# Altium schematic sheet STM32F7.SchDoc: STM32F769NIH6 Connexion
size A3; Date: 29-OCT-2015; Author: A.B; CompanyName: STMicroelectronics; Organization: MCD/TOOLS/GNB; Address1: 12, Rue Jules HOROWITZ; Address2: 38019 Grenoble; Address3: FRANCE; DocumentNumber: MB1225; Revision: B-01; SheetNumber: 4; SheetTotal: 13; Project: STM32F769I-DISCO
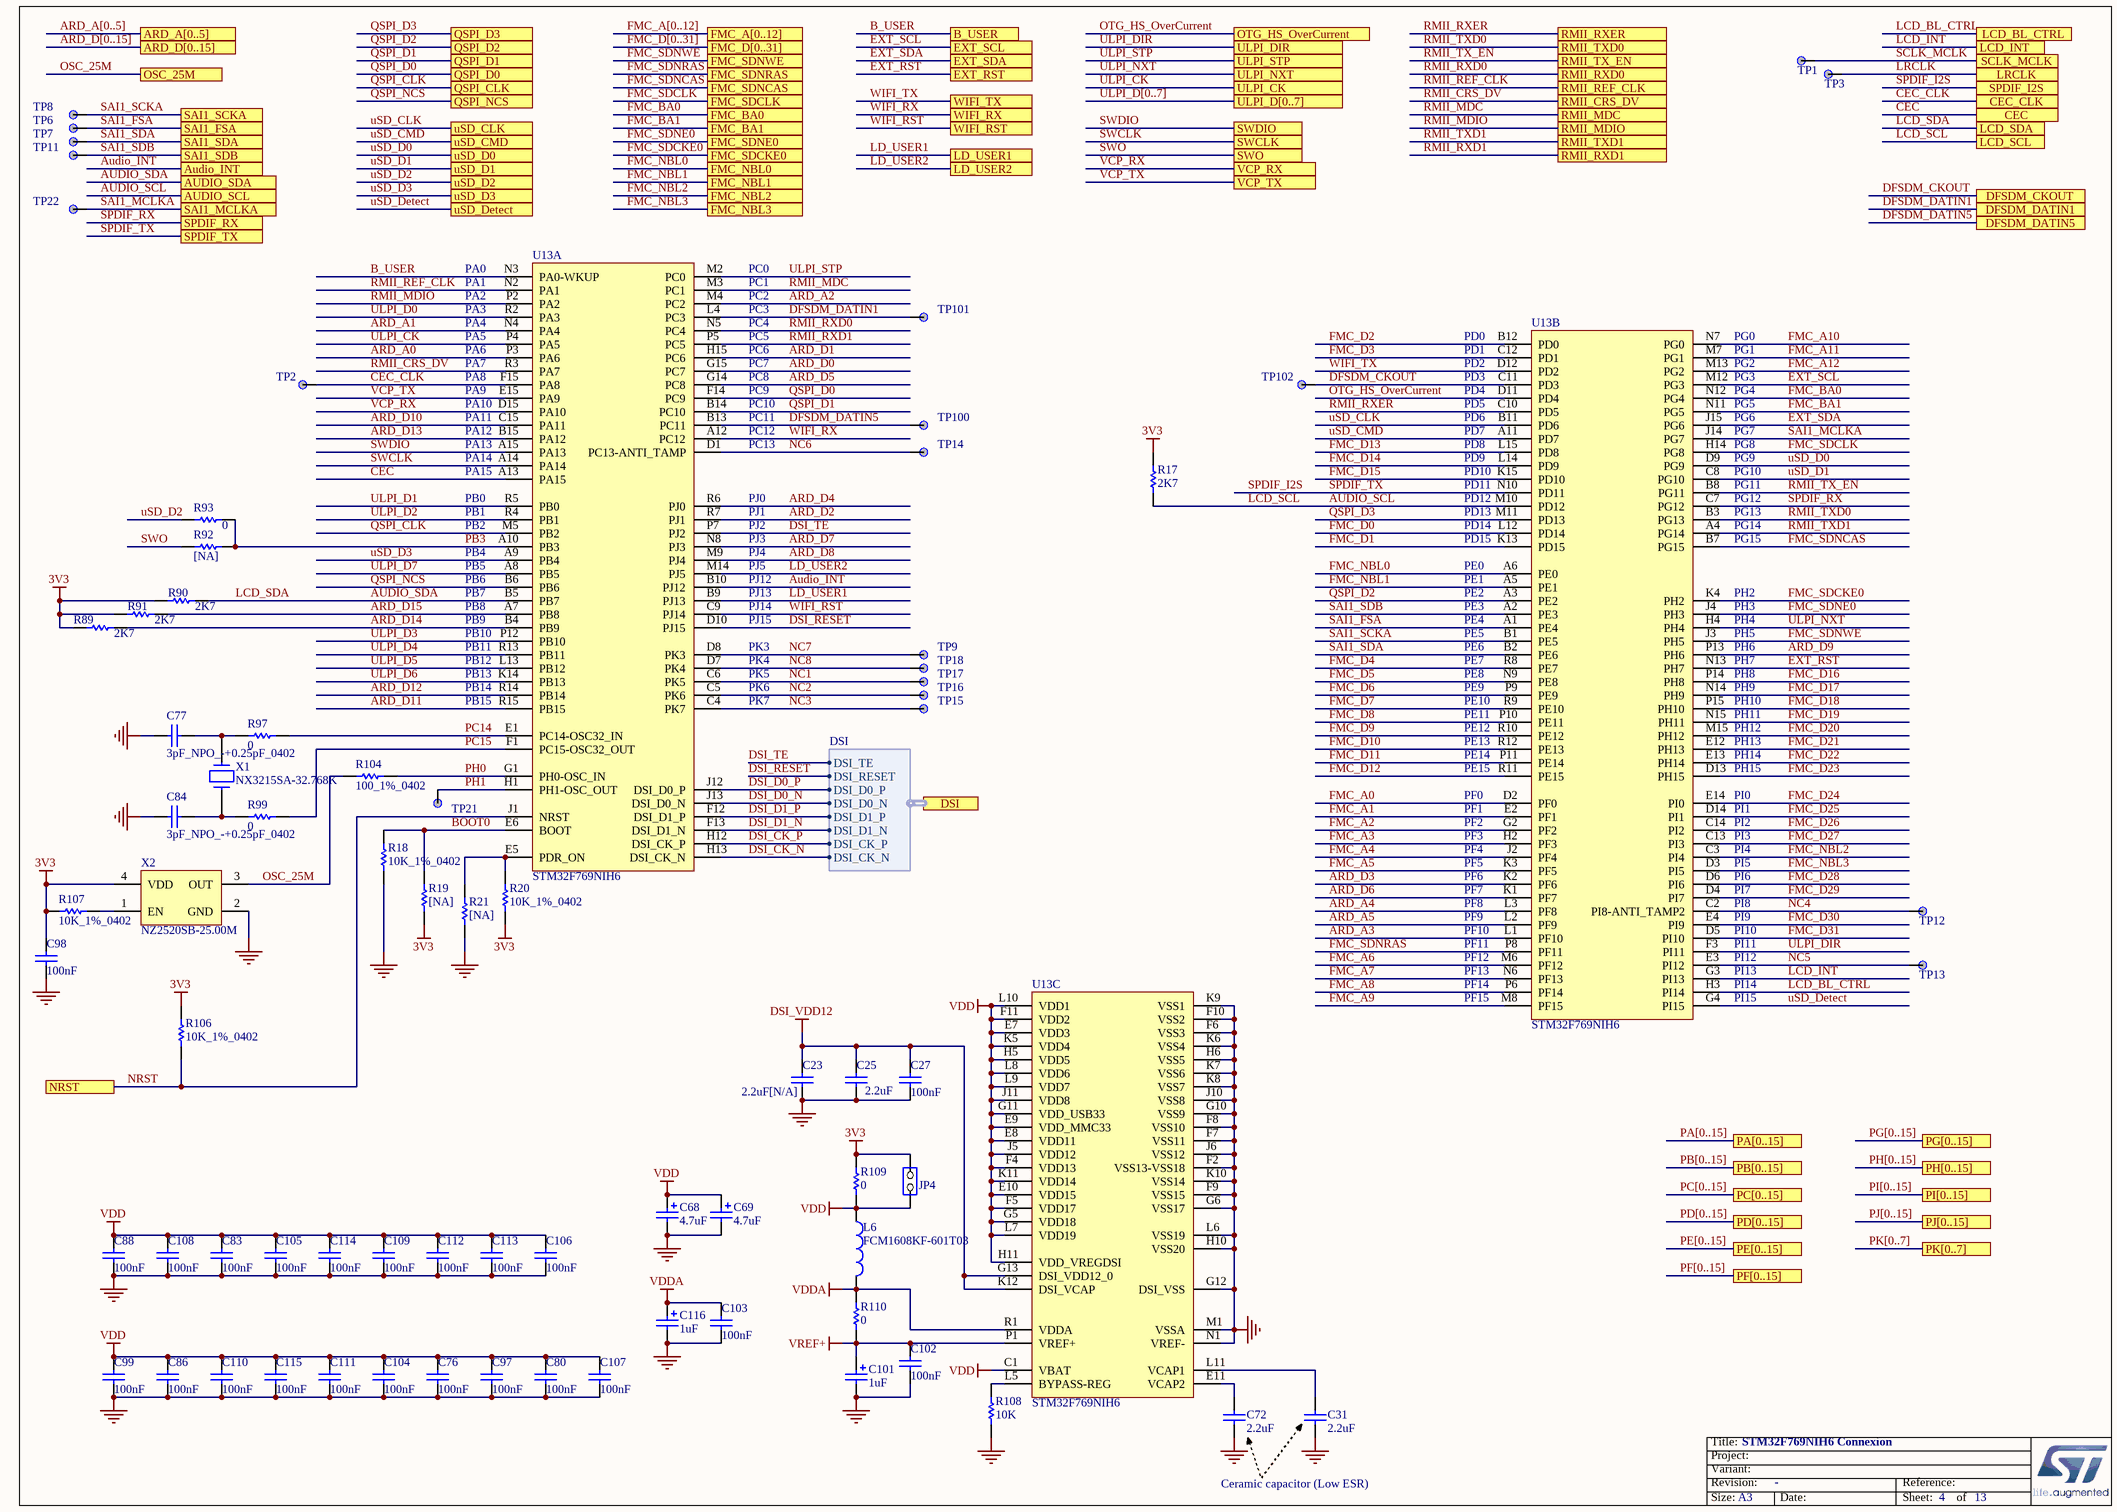
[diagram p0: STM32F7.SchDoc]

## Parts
C23  2.2uF[N/A]  [1206C]
C25  2.2uF  [0603C]
C27  100nF  [0402C]
C31  2.2uF  [1206C]
C68  4.7uF  [TAN-A]
C69  4.7uF  [TAN-A]
C72  2.2uF  [1206C]
C76  100nF  [0402C]
C77  3pF_NPO_-+0.25pF_0402  [0402C]
C80  100nF  [0402C]
C83  100nF  [0402C]
C84  3pF_NPO_-+0.25pF_0402  [0402C]
C86  100nF  [0402C]
C88  100nF  [0402C]
C97  100nF  [0402C]
C98  100nF  [0402C]
C99  100nF  [0402C]
C101  1uF  [TAN-A]
C102  100nF  [0402C]
C103  100nF  [0402C]
C104  100nF  [0402C]
C105  100nF  [0402C]
C106  100nF  [0402C]
C107  100nF  [0402C]
C108  100nF  [0402C]
C109  100nF  [0402C]
C110  100nF  [0402C]
C111  100nF  [0402C]
C112  100nF  [0402C]
C113  100nF  [0402C]
C114  100nF  [0402C]
C115  100nF  [0402C]
C116  1uF  [TAN-A]
JP4  JP2  [SIP2]  (value not drawn)
L6  FCM1608KF-601T03  [0603L]
R17  2K7  [0402R]
R18  10K_1%_0402  [0402R]
R19  [NA]  [0402R]
R20  10K_1%_0402  [0402R]
R21  [NA]  [0402R]
R89  2K7  [0402R]
R90  2K7  [0402R]
R91  2K7  [0402R]
R92  [NA]  [0402R]
R93  0  [0402R]
R97  0  [0402R]
R99  0  [0402R]
R104  100_1%_0402  [0402R]
R106  10K_1%_0402  [0402R]
R107  10K_1%_0402  [0402R]
R108  10K  [0402R]
R109  0  [0603R-GS]
R110  0  [0603R-GS]
TP1  TP  [TP_C40]  (value not drawn)
TP2  TP  [TP_C40]  (value not drawn)
TP3  TP  [TP_C40]  (value not drawn)
TP6  TP  [TP_C40]  (value not drawn)
TP7  TP  [TP_C40]  (value not drawn)
TP8  TP  [TP_C40]  (value not drawn)
TP9  TP  [TP_C40]  (value not drawn)
TP11  TP  [TP_C40]  (value not drawn)
TP12  TP  [TP_C40]  (value not drawn)
TP13  TP  [TP_C40]  (value not drawn)
TP14  TP  [TP_C40]  (value not drawn)
TP15  TP  [TP_C40]  (value not drawn)
TP16  TP  [TP_C40]  (value not drawn)
TP17  TP  [TP_C40]  (value not drawn)
TP18  TP  [TP_C40]  (value not drawn)
TP21  TP  [TP_C40]  (value not drawn)
TP22  TP  [TP_C40]  (value not drawn)
TP100  TP  [TP_C40]  (value not drawn)
TP101  TP  [TP_C40]  (value not drawn)
TP102  TP  [TP_C40]  (value not drawn)
U13  STM32F769NIH6  [BGA216_0R8_13X13]  (parts A,B,C of 3)
X1  NX3215SA-32.768K  [XTAL_2SM_3R2X1R5]
X2  NZ2520SB-25.00M  [OSC_4SM_2R5X2]

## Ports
ARD_A[0..5], ARD_D[0..15], Audio_INT, AUDIO_SCL, AUDIO_SDA, B_USER, CEC, CEC_CLK, DFSDM_CKOUT, DFSDM_DATIN1, DFSDM_DATIN5, DSI (harness DSI), EXT_RST, EXT_SCL, EXT_SDA, FMC_A[0..12], FMC_BA0, FMC_BA1, FMC_D[0..31], FMC_NBL0, FMC_NBL1, FMC_NBL2, FMC_NBL3, FMC_SDCKE0, FMC_SDCLK, FMC_SDNCAS, FMC_SDNE0, FMC_SDNRAS, FMC_SDNWE, LCD_BL_CTRL, LCD_INT, LCD_SCL, LCD_SDA, LD_USER1, LD_USER2, LRCLK, NRST, OSC_25M, OTG_HS_OverCurrent, PA[0..15], PB[0..15], PC[0..15], PD[0..15], PE[0..15], PF[0..15], PG[0..15], PH[0..15], PI[0..15], PJ[0..15], PK[0..7], QSPI_CLK, QSPI_D0, QSPI_D1, QSPI_D2, QSPI_D3, QSPI_NCS, RMII_CRS_DV, RMII_MDC, RMII_MDIO, RMII_REF_CLK, RMII_RXD0, RMII_RXD1, RMII_RXER, RMII_TX_EN, RMII_TXD0, RMII_TXD1, SAI1_FSA, SAI1_MCLKA, SAI1_SCKA, SAI1_SDA, SAI1_SDB, SCLK_MCLK, SPDIF_I2S, SPDIF_RX, SPDIF_TX, SWCLK, SWDIO, SWO, ULPI_CK, ULPI_D[0..7], ULPI_DIR, ULPI_NXT, ULPI_STP, uSD_CLK, uSD_CMD, uSD_D0, uSD_D1, uSD_D2, uSD_D3, uSD_Detect, VCP_RX, VCP_TX, WIFI_RST, WIFI_RX, WIFI_TX

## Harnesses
DSI: DSI_CK_P, DSI_CK_N, DSI_D0_P, DSI_D0_N, DSI_D1_P, DSI_D1_N, DSI_TE, DSI_RESET

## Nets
3V3: C98.2 JP4.2(NO) R17.2 R19.1 R20.1 R89.1 R90.1 R91.1 R106.2 R107.1 R109.2 X2.4(VDD)
DSI_VDD12: C23.2 C25.2 C27.2 U13.G13(DSI_VDD12_0) U13.K12(DSI_VCAP)
GND: C23.1 C25.1 C27.1 C31.1 C68.2 C69.2 C72.1 C76.1 C77.1 C80.1 C83.1 C84.1 C86.1 C88.1 C97.1 C98.1 C99.1 C101.2 C102.1 C103.1 C104.1 C105.1 C106.1 C107.1 C108.1 C109.1 C110.1 C111.1 C112.1 C113.1 C114.1 C115.1 C116.2 R18.1 R21.1 R108.1 U13.F2(VSS13-VSS18) U13.F6(VSS3) U13.F7(VSS11) U13.F8(VSS10) U13.F9(VSS15) U13.F10(VSS2) U13.G6(VSS17) U13.G10(VSS9) U13.G12(DSI_VSS) U13.H6(VSS5) U13.H10(VSS20) U13.J6(VSS12) U13.J10(VSS8) U13.K6(VSS4) U13.K7(VSS6) U13.K8(VSS7) U13.K9(VSS1) U13.K10(VSS14) U13.L6(VSS19) U13.M1(VSSA) U13.N1(VREF-) X2.2(GND)
VDD: C68.1 C69.1 C76.2 C80.2 C83.2 C86.2 C88.2 C97.2 C99.2 C104.2 C105.2 C106.2 C107.2 C108.2 C109.2 C110.2 C111.2 C112.2 C113.2 C114.2 C115.2 JP4.1(COMMON) L6.1 R109.1 U13.C1(VBAT) U13.E7(VDD3) U13.E8(VDD11) U13.E9(VDD_MMC33) U13.E10(VDD15) U13.F4(VDD13) U13.F5(VDD17) U13.F11(VDD2) U13.G5(VDD18) U13.G11(VDD_USB33) U13.H5(VDD5) U13.H11(VDD_VREGDSI) U13.J5(VDD12) U13.J11(VDD8) U13.K5(VDD4) U13.K11(VDD14) U13.L7(VDD19) U13.L8(VDD6) U13.L9(VDD7) U13.L10(VDD1)
VDDA: C103.2 C116.1 L6.2 R110.1 U13.R1(VDDA)
VREF+: C101.1 C102.2 R110.2 U13.P1(VREF+)
ARD_A0: U13.P3(PA6)
ARD_A1: U13.N4(PA4)
ARD_A2: U13.M4(PC2)
ARD_A3: U13.L1(PF10)
ARD_A4: U13.L3(PF8)
ARD_A5: U13.L2(PF9)
ARD_D0: U13.G15(PC7)
ARD_D1: U13.H15(PC6)
ARD_D2: U13.R7(PJ1)
ARD_D3: U13.K2(PF6)
ARD_D4: U13.R6(PJ0)
ARD_D5: U13.G14(PC8)
ARD_D6: U13.K1(PF7)
ARD_D7: U13.N8(PJ3)
ARD_D8: U13.M9(PJ4)
ARD_D9: U13.P13(PH6)
ARD_D10: U13.C15(PA11)
ARD_D11: U13.R15(PB15)
ARD_D12: U13.R14(PB14)
ARD_D13: U13.B15(PA12)
ARD_D14: R89.2 U13.B4(PB9)
ARD_D15: R91.2 U13.A7(PB8)
Audio_INT: U13.B10(PJ12) ; port Audio_INT
AUDIO_SCL: R17.1 U13.M10(PD12) ; port AUDIO_SCL, port LCD_SCL  [also labelled LCD_SCL]
AUDIO_SDA: R90.2 U13.B5(PB7) ; port AUDIO_SDA, port LCD_SDA  [also labelled LCD_SDA]
B_USER: U13.N3(PA0-WKUP) ; port B_USER
BOOT0: R18.2 R19.2 U13.E6(BOOT)
CEC: U13.A13(PA15) ; port CEC
CEC_CLK: TP2.1 U13.F15(PA8) ; port CEC_CLK
DFSDM_CKOUT: TP102.1 U13.C11(PD3) ; port DFSDM_CKOUT
DFSDM_DATIN1: TP101.1 U13.L4(PC3) ; port DFSDM_DATIN1
DFSDM_DATIN5: TP100.1 U13.B13(PC11) ; port DFSDM_DATIN5
DSI_CK_N: U13.H13(DSI_CK_N) ; port DSI.DSI_CK_N
DSI_CK_P: U13.H12(DSI_CK_P) ; port DSI.DSI_CK_P
DSI_D0_N: U13.J13(DSI_D0_N) ; port DSI.DSI_D0_N
DSI_D0_P: U13.J12(DSI_D0_P) ; port DSI.DSI_D0_P
DSI_D1_N: U13.F13(DSI_D1_N) ; port DSI.DSI_D1_N
DSI_D1_P: U13.F12(DSI_D1_P) ; port DSI.DSI_D1_P
DSI_RESET: U13.D10(PJ15) ; port DSI.DSI_RESET
DSI_TE: U13.P7(PJ2) ; port DSI.DSI_TE
EXT_RST: U13.N13(PH7) ; port EXT_RST
EXT_SCL: U13.M12(PG3) ; port EXT_SCL
EXT_SDA: U13.J15(PG6) ; port EXT_SDA
FMC_A0: U13.D2(PF0)
FMC_A1: U13.E2(PF1)
FMC_A2: U13.G2(PF2)
FMC_A3: U13.H2(PF3)
FMC_A4: U13.J2(PF4)
FMC_A5: U13.K3(PF5)
FMC_A6: U13.M6(PF12)
FMC_A7: U13.N6(PF13)
FMC_A8: U13.P6(PF14)
FMC_A9: U13.M8(PF15)
FMC_A10: U13.N7(PG0)
FMC_A11: U13.M7(PG1)
FMC_A12: U13.M13(PG2)
FMC_BA0: U13.N12(PG4) ; port FMC_BA0
FMC_BA1: U13.N11(PG5) ; port FMC_BA1
FMC_D0: U13.L12(PD14)
FMC_D1: U13.K13(PD15)
FMC_D2: U13.B12(PD0)
FMC_D3: U13.C12(PD1)
FMC_D4: U13.R8(PE7)
FMC_D5: U13.N9(PE8)
FMC_D6: U13.P9(PE9)
FMC_D7: U13.R9(PE10)
FMC_D8: U13.P10(PE11)
FMC_D9: U13.R10(PE12)
FMC_D10: U13.R12(PE13)
FMC_D11: U13.P11(PE14)
FMC_D12: U13.R11(PE15)
FMC_D13: U13.L15(PD8)
FMC_D14: U13.L14(PD9)
FMC_D15: U13.K15(PD10)
FMC_D16: U13.P14(PH8)
FMC_D17: U13.N14(PH9)
FMC_D18: U13.P15(PH10)
FMC_D19: U13.N15(PH11)
FMC_D20: U13.M15(PH12)
FMC_D21: U13.E12(PH13)
FMC_D22: U13.E13(PH14)
FMC_D23: U13.D13(PH15)
FMC_D24: U13.E14(PI0)
FMC_D25: U13.D14(PI1)
FMC_D26: U13.C14(PI2)
FMC_D27: U13.C13(PI3)
FMC_D28: U13.D6(PI6)
FMC_D29: U13.D4(PI7)
FMC_D30: U13.E4(PI9)
FMC_D31: U13.D5(PI10)
FMC_NBL0: U13.A6(PE0) ; port FMC_NBL0
FMC_NBL1: U13.A5(PE1) ; port FMC_NBL1
FMC_NBL2: U13.C3(PI4) ; port FMC_NBL2
FMC_NBL3: U13.D3(PI5) ; port FMC_NBL3
FMC_SDCKE0: U13.K4(PH2) ; port FMC_SDCKE0
FMC_SDCLK: U13.H14(PG8) ; port FMC_SDCLK
FMC_SDNCAS: U13.B7(PG15) ; port FMC_SDNCAS
FMC_SDNE0: U13.J4(PH3) ; port FMC_SDNE0
FMC_SDNRAS: U13.P8(PF11) ; port FMC_SDNRAS
FMC_SDNWE: U13.J3(PH5) ; port FMC_SDNWE
LCD_BL_CTRL: U13.H3(PI14) ; port LCD_BL_CTRL
LCD_INT: U13.G3(PI13) ; port LCD_INT
LD_USER1: U13.B9(PJ13) ; port LD_USER1
LD_USER2: U13.M14(PJ5) ; port LD_USER2
LRCLK: TP3.1 ; port LRCLK
NC1: TP17.1 U13.C6(PK5)
NC2: TP16.1 U13.C5(PK6)
NC3: TP15.1 U13.C4(PK7)
NC4: TP12.1 U13.C2(PI8-ANTI_TAMP2)
NC5: TP13.1 U13.E3(PI12)
NC6: TP14.1 U13.D1(PC13-ANTI_TAMP)
NC7: TP9.1 U13.D8(PK3)
NC8: TP18.1 U13.D7(PK4)
NRST: R106.1 U13.J1(NRST) ; port NRST
OSC_25M: R104.1 X2.3(OUT) ; port OSC_25M
OTG_HS_OverCurrent: U13.D11(PD4) ; port OTG_HS_OverCurrent
PB3: R92.2 R93.2 U13.A10(PB3)
PC14: R97.2 U13.E1(PC14-OSC32_IN)
PC15: R99.2 U13.F1(PC15-OSC32_OUT)
PH0: R104.2 U13.G1(PH0-OSC_IN)
PH1: TP21.1 U13.H1(PH1-OSC_OUT)
QSPI_CLK: U13.M5(PB2) ; port QSPI_CLK
QSPI_D0: U13.F14(PC9) ; port QSPI_D0
QSPI_D1: U13.B14(PC10) ; port QSPI_D1
QSPI_D2: U13.A3(PE2) ; port QSPI_D2
QSPI_D3: U13.M11(PD13) ; port QSPI_D3
QSPI_NCS: U13.B6(PB6) ; port QSPI_NCS
RMII_CRS_DV: U13.R3(PA7) ; port RMII_CRS_DV
RMII_MDC: U13.M3(PC1) ; port RMII_MDC
RMII_MDIO: U13.P2(PA2) ; port RMII_MDIO
RMII_REF_CLK: U13.N2(PA1) ; port RMII_REF_CLK
RMII_RXD0: U13.N5(PC4) ; port RMII_RXD0
RMII_RXD1: U13.P5(PC5) ; port RMII_RXD1
RMII_RXER: U13.C10(PD5) ; port RMII_RXER
RMII_TX_EN: U13.B8(PG11) ; port RMII_TX_EN
RMII_TXD0: U13.B3(PG13) ; port RMII_TXD0
RMII_TXD1: U13.A4(PG14) ; port RMII_TXD1
SAI1_FSA: TP6.1 U13.A1(PE4) ; port SAI1_FSA
SAI1_MCLKA: TP22.1 U13.J14(PG7) ; port SAI1_MCLKA
SAI1_SCKA: TP8.1 U13.B1(PE5) ; port SAI1_SCKA
SAI1_SDA: TP7.1 U13.B2(PE6) ; port SAI1_SDA
SAI1_SDB: TP11.1 U13.A2(PE3) ; port SAI1_SDB
SCLK_MCLK: TP1.1 ; port SCLK_MCLK
SPDIF_I2S: U13.N10(PD11) ; port SPDIF_TX, port SPDIF_I2S  [also labelled SPDIF_TX]
SPDIF_RX: U13.C7(PG12) ; port SPDIF_RX
SWCLK: U13.A14(PA14) ; port SWCLK
SWDIO: U13.A15(PA13) ; port SWDIO
SWO: R92.1 ; port SWO
ULPI_CK: U13.P4(PA5) ; port ULPI_CK
ULPI_D0: U13.R2(PA3)
ULPI_D1: U13.R5(PB0)
ULPI_D2: U13.R4(PB1)
ULPI_D3: U13.P12(PB10)
ULPI_D4: U13.R13(PB11)
ULPI_D5: U13.L13(PB12)
ULPI_D6: U13.K14(PB13)
ULPI_D7: U13.A8(PB5)
ULPI_DIR: U13.F3(PI11) ; port ULPI_DIR
ULPI_NXT: U13.H4(PH4) ; port ULPI_NXT
ULPI_STP: U13.M2(PC0) ; port ULPI_STP
uSD_CLK: U13.B11(PD6) ; port uSD_CLK
uSD_CMD: U13.A11(PD7) ; port uSD_CMD
uSD_D0: U13.D9(PG9) ; port uSD_D0
uSD_D1: U13.C8(PG10) ; port uSD_D1
uSD_D2: R93.1 ; port uSD_D2
uSD_D3: U13.A9(PB4) ; port uSD_D3
uSD_Detect: U13.G4(PI15) ; port uSD_Detect
VCP_RX: U13.D15(PA10) ; port VCP_RX
VCP_TX: U13.E15(PA9) ; port VCP_TX
WIFI_RST: U13.C9(PJ14) ; port WIFI_RST
WIFI_RX: U13.A12(PC12) ; port WIFI_RX
WIFI_TX: U13.D12(PD2) ; port WIFI_TX
NetC31_2: C31.2 U13.L11(VCAP1)
NetC72_2: C72.2 U13.E11(VCAP2)
NetC77_2: C77.2 R97.1 X1.1
NetC84_2: C84.2 R99.1 X1.2
NetR20_2: R20.2 R21.2 U13.E5(PDR_ON)
NetR107_2: R107.2 X2.1(EN)
NetR108_2: R108.2 U13.L5(BYPASS-REG)

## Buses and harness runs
bus ARD_A[0..5] = port ARD_A[0..5]
bus ARD_D[0..15] = port ARD_D[0..15]
bus FMC_A[0..12] = port FMC_A[0..12]
bus FMC_D[0..31] = port FMC_D[0..31]
bus PA[0..15] = port PA[0..15]
bus PB[0..15] = port PB[0..15]
bus PC[0..15] = port PC[0..15]
bus PD[0..15] = port PD[0..15]
bus PE[0..15] = port PE[0..15]
bus PF[0..15] = port PF[0..15]
bus PG[0..15] = port PG[0..15]
bus PH[0..15] = port PH[0..15]
bus PI[0..15] = port PI[0..15]
bus PJ[0..15] = port PJ[0..15]
bus PK[0..7] = port PK[0..7]
bus ULPI_D[0..7] = port ULPI_D[0..7]

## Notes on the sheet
- (near U13) PA3
- (near U13) PA2
- (near U13) PA1
- (near U13) PA0
- PC0
- PC1
- PC2
- PC3
- (near U13) PA6
- (near U13) PA5
- (near U13) PA4
- (near U13) PA7
- (near U13) PA8
- PC4
- PC5
- PC6
- PC7
- PC8
- (near U13) PD0
- (near U13) PD1
- (near U13) PD2
- (near U13) PD3
- (near U13) PG0
- (near U13) PG1
- (near U13) PG2
- (near U13) PG3
- (near U13) PA9
- (near U13) PA10
- (near U13) PA11
- (near U13) PA12
- (near U13) PA13
- PC9
- PC10
- PC11
- PC12
- PC13
- (near U13) PD4
- (near U13) PD5
- (near U13) PD6
- (near U13) PD7
- (near U13) PD8
- (near U13) PG4
- (near U13) PG5
- (near U13) PG6
- (near U13) PG7
- (near U13) PG8
- (near U13) PA14
- (near U13) PA15
- (near U13) PB1
- (near U13) PB0
- PJ0
- PJ1
- (near U13) PD9
- (near U13) PD10
- (near U13) PD11
- (near U13) PD12
- (near U13) PD13
- (near U13) PG9
- (near U13) PG10
- (near U13) PG11
- (near U13) PG12
- (near U13) PG13
- (near U13) PB6
- (near U13) PB5
- (near U13) PB4
- (near U13) PB2
- PJ2
- PJ3
- PJ4
- PJ5
- PJ12
- (near U13) PD14
- (near U13) PD15
- (near U13) PE0
- (near U13) PE1
- (near U13) PG14
- (near U13) PG15
- (near U13) PB7
- (near U13) PB8
- (near U13) PB9
- (near U13) PB10
- (near U13) PB11
- PJ13
- PJ14
- PJ15
- PK3
- (near U13) PE2
- (near U13) PE3
- (near U13) PE4
- (near U13) PE5
- (near U13) PE6
- (near U13) PH2
- (near U13) PH3
- (near U13) PH4
- (near U13) PH5
- (near U13) PH6
- (near U13) PB12
- (near U13) PB13
- (near U13) PB14
- (near U13) PB15
- PK4
- PK5
- PK6
- PK7
- (near U13) PE7
- (near U13) PE8
- (near U13) PE9
- (near U13) PE10
- (near U13) PE11
- (near U13) PH7
- (near U13) PH8
- (near U13) PH9
- (near U13) PH10
- (near U13) PH11
- (near U13) PE12
- (near U13) PE13
- (near U13) PE14
- (near U13) PE15
- (near U13) PH12
- (near U13) PH13
- (near U13) PH14
- (near U13) PH15
- (near U13) PF0
- (near U13) PF1
- (near U13) PF2
- (near U13) PF3
- (near U13) PF4
- (near U13) PI0
- (near U13) PI1
- (near U13) PI2
- (near U13) PI3
- (near U13) PI4
- (near U13) PF5
- (near U13) PF6
- (near U13) PF7
- (near U13) PF8
- (near U13) PF9
- (near U13) PI5
- (near U13) PI6
- (near U13) PI7
- (near U13) PI8
- (near U13) PI9
- (near U13) PF10
- (near U13) PF11
- (near U13) PF12
- (near U13) PF13
- (near U13) PF14
- (near U13) PI10
- (near U13) PI11
- (near U13) PI12
- (near U13) PI13
- (near U13) PI14
- (near U13) PF15
- (near U13) PI15
- Ceramic capacitor (Low ESR)

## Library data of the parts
C23 = Cap_2.2uF_X7R_10%_1206: Capacitor,2.2uF,16V, X7R,10%,1206,YAGEO; Manuf_Part_1: CC1206KKX7R7BB225; Manuf_Part_2: C1206C225K4RAC; Manuf_2: KEMET; Fitted: NO
C25 = Cap_2.2uF_X5R_10%_0603: Capacitor,2.2uF,10V, X5R,10%,0603,YAGEO; Manuf_Part_1: CC0603KRX5R6BB225; Manuf_Part_2: C0603C225K8PACTU; Manuf_2: KEMET
C27 C76 C80 C83 C86 C88 C97-C99 C102-C115 = Cap_100nF_X7R_10%_0402: Capacitor,100nF,16V,X7R,10%,0402,YAGEO; Manuf_Part_1: CC0402KRX7R7BB104
C31 C72 = Cap_2.2uF_X7R_10%_1206: Capacitor,2.2uF,16V, X7R,10%,1206,YAGEO; Manuf_Part_1: CC1206KKX7R7BB225; Manuf_Part_2: C1206C225K4RAC; Manuf_2: KEMET
C68 C69 = Cap_4.7uF_POL_10%_TANA: Polarized Capacitor,4.7uF,16V,10%,typeA,AVX; Manuf_Part_1: TAJA475K016R
C77 C84 = Cap_4.3pF_NPO_-+0.25pF_0402: Capacitor, 3pF, 16V, NPO, -+0.25pF, 0402, KEMET; Manuf_1: AVX; Manuf_Part_1: C0402C439C4GACTU; Order: C0402C439C4GACTU-ND
C101 C116 = Cap_1uF_POL_10%_TANA: Polarized Capacitor,1uF,16V,10%,typeA,AVX; Manuf_Part_1: TAJA105K016R
JP4 = JP2: Fitted: NO
L6 = BEAD_600R_350MA_0603: Bead,600R,350mA,0603,FCM1608KF-601T03,Tai-tech; Manuf_2: TDK; Manuf_Part_2: MPZ1608S300A; Manuf_Part_3: BLM18PG121SN1D; Manuf_3: MURATA; Value: 100uH; Description_2: Bead,30R,5A,0603,MPZ1608S300A,TDK; Description_3: Bead,120R,2A,0603,BLM18PG121SN1D,MURATA
R17 R89-R91 = Res_2K7_1%_0402: Resistor,2K7,0402,1%,YAGEO; Manuf_Part_1: RC0402FR-072K7L
R18 R20 R106-R108 = Res_10K_1%_0402: Resistor,10K,0402,1%,YAGEO; Manuf_Part_1: RC0402FR-0710KL
R19 R21 R92 = Res_NA_0402: Resistor,[NA],0402; Fitted: NO
R93 R97 R99 = Res_0_5%_0402: Resistor,0,0402,5%,YAGEO; Manuf_Part_1: RC0402JR-070RL; Order: 2363467
R104 = Res_100_1%_0402: Resistor,100,0402,1%,YAGEO; Manuf_Part_1: RC0402FR-07100RL; Value: 100; Order: 9239111
R109 R110 = Res_0_5%_0603: Resistor,0,0603,5%,YAGEO; Manuf_Part_1: RC0603JR-070RL; Order: 2363481
TP1-TP3 TP6-TP9 TP11-TP18 TP21 TP22 TP100-TP102 = TP: Test Point
U13 = STM32F769NIH6U: STM32F769NIH6 (STM32F7 Big Birdie) TBGA216; Manuf_1: STM; ECCN_US/EU: 3A991A2/NEC; Ref St: xxxxxxxx; Provided: ST
X1 = XTAL_32K_NX3215SA: Crystal 32.768kHz, 6pF, -+20PPM, R=50K, SMD; Manuf_1: NDK; Manuf_Part_1: NX3215SA 32.768KHz EXS00A-MU00525; ECCN_US/EU: EAR99/NEC; Ref St: 9157034; NDK Ref: X3101802; Provided: ST
X2 = OSC_25M_NZ2520SB: Oscillator 25.00Mhz, -+50PPM, 3.3V, Temp -55 to +125°C; Manuf_Part_1: NZ2520SB 25MHz END4869B; Manuf_1: NDK; Manuf_Part_2: KC2520B25.0000C10E00; Manuf_2: AVX Corp/Kyocera Corp; ECCN_US/EU: EAR99/NEC; Ref St: 9157031; Provided: ST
